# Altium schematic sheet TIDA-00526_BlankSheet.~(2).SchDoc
size 431 x 279 mm; Date: Not shown in title block; ApprovedBy: Not shown in title block; CheckedBy: Not shown in title block; Author: Not shown in title block; CompanyName: Texas Instruments; Engineer: Antony Carvajales; Organization: MDP_RF; Address1: Not shown in title block; Address2: Not shown in title block; Address3: Not shown in title block; Address4: Not shown in title block; DocumentNumber: 1; Revision: Use project parameter SCH_Rev; SheetNumber: 2; SheetTotal: 3; PageSetup: Record=PageOptions¦CenterHorizontal=True¦CenterVertical=True¦PrintScale=1.00¦XCorrection=1.00¦YCorrection=1.00¦PrintKind=0¦BorderSize=5000000¦LeftOffset=0¦BottomOffset=0¦Orientation=2¦PaperLength=1000¦PaperWidth=1000¦Scale=100¦PaperSource=15¦PrintQuality=-3¦MediaType=1¦DitherType=10¦PrintScaleMode=1¦PaperKind=Letter¦PaperIndex=1
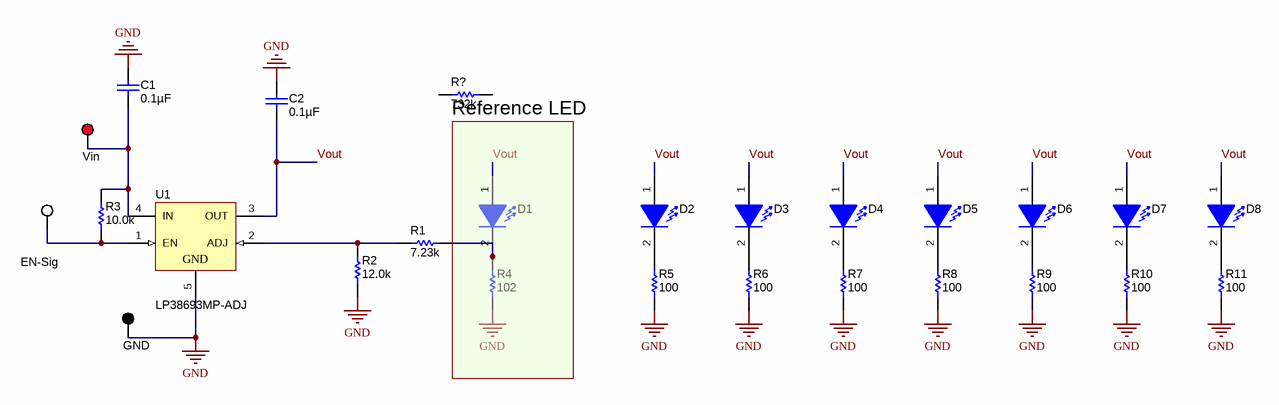
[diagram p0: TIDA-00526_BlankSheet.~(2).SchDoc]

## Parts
C1  ValueDisplayed: 0.1µF  [0805_HV]  (hidden comment: C0805C104K3RACTU)
C2  ValueDisplayed: 0.1µF  [0805_HV]  (hidden comment: C0805C104K3RACTU)
D1  C503D-WAN-CCBDB232  [HLMP-341_YELLOW]  (value not drawn)
D2  C503D-WAN-CCBDB232  [HLMP-341_YELLOW]  (value not drawn)
D3  LED, White, TH  [HLMP-341_YELLOW]  (value not drawn)
D4  C503D-WAN-CCBDB232  [HLMP-341_YELLOW]  (value not drawn)
D5  C503D-WAN-CCBDB232  [HLMP-341_YELLOW]  (value not drawn)
D6  C503D-WAN-CCBDB232  [HLMP-341_YELLOW]  (value not drawn)
D7  C503D-WAN-CCBDB232  [HLMP-341_YELLOW]  (value not drawn)
D8  C503D-WAN-CCBDB232  [HLMP-341_YELLOW]  (value not drawn)
EN-Sig  5002  [Keystone5002]  (value not drawn)
GND  5001  [Keystone5001]  (value not drawn)
R1  ValueDisplayed: 7.23k  [0603]  (hidden comment: RT0603DRE077K23L)
R2  ValueDisplayed: 12.0k  [0603]  (hidden comment: RC0603FR-0712KL)
R3  ValueDisplayed: 10.0k  [0603]  (hidden comment: CRCW060310K0FKEA)
R4  ValueDisplayed: 102  [0603]  (hidden comment: CRCW0603102RFKEA)
R5  ValueDisplayed: 100  [0603]  (hidden comment: RC0603FR-07100RL)
R6  ValueDisplayed: 100  [0603]  (hidden comment: RC0603FR-07100RL)
R7  ValueDisplayed: 100  [0603]  (hidden comment: RC0603FR-07100RL)
R8  ValueDisplayed: 100  [0603]  (hidden comment: RC0603FR-07100RL)
R9  ValueDisplayed: 100  [0603]  (hidden comment: RC0603FR-07100RL)
R10  ValueDisplayed: 100  [0603]  (hidden comment: RC0603FR-07100RL)
R11  ValueDisplayed: 100  [0603]  (hidden comment: RC0603FR-07100RL)
R?  ValueDisplayed: 732k  [0603]  (hidden comment: RC0603FR-07732KL)
U1  LP38693MP-ADJ  [MP05A_N]
Vin  5000  [Keystone5000]  (value not drawn)

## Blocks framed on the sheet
Reference LED: D1 R4

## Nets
GND: C1.1 C2.1 GND.1 R2.1 R4.1 R5.1 R6.1 R7.1 R8.1 R9.1 R10.1 R11.1 U1.5(GND)
Vout: C2.2 D1.1(A) D2.1(A) D3.1(A) D4.1(A) D5.1(A) D6.1(A) D7.1(A) D8.1(A) U1.3(OUT)
NetC1_2: C1.2 R3.2 U1.4(IN) Vin.1
NetD1_2: D1.2(K) R1.2 R4.2
NetD2_2: D2.2(K) R5.2
NetD3_2: D3.2(K) R6.2
NetD4_2: D4.2(K) R7.2
NetD5_2: D5.2(K) R8.2
NetD6_2: D6.2(K) R9.2
NetD7_2: D7.2(K) R10.2
NetD8_2: D8.2(K) R11.2
NetEN-Sig_1: EN-Sig.1 R3.1 U1.1(EN)
NetR1_1: R1.1 R2.2 U1.2(ADJ)

Not connected (* = marked no-connect by the designer): R? 1 2

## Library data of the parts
C1 C2 = C0805C104K3RACTU: CAP, CERM, 0.1 µF, 25 V, +/- 10%, X7R, 0805; Manufacturer: Kemet; Polarized: N; CompType: Capacitor; Value: 0.1uF; U/M: EA; Cap_F: 0.0000001; Tolerance_%: 10; ESR_ohm: 0.064; Value1: 0.064 ohm; VDC_V: 25; Value2: 25V; IRMS_A: 1.64; TaMin_C: -55; TaMax_C: 125; Cap_Case: 0805
D1 D2 D4 D5 D7 D8 = HLMP-3416: LED, White, TH; Manufacturer: CREE
D3 = HLMP-3416: Manufacturer: CREE; PartNumber: C503D-WAN-CCBDB232
D6 = HLMP-3416: LED, white, TH; Manufacturer: CREE
EN-Sig = 5002: Test Point, Miniature, White, TH; Manufacturer: Keystone; CompType: Test Point Loop; U/M: EA
GND = 5001: Test Point, Miniature, Black, TH; Manufacturer: Keystone; CompType: Test Point Loop; U/M: EA
R1 = RT0603DRE077K23L: RES, 7.23 k, 0.5%, 0.1 W, 0603; Manufacturer: Yageo America; CompType: Resistor; Value: 7.23k; Res_ohm: 7230; Value_Code: 7k23; Tolerance_%: 0.5; Power_W: 0.1; Value2: 0.1W; VDC_V: 75; TempCo: 50 ppm/C; EIA_Code: E192; U/M: EA
R2 = RC0603FR-0712KL: RES, 12.0 k, 1%, 0.1 W, 0603; Manufacturer: Yageo America; CompType: Resistor; Value: 12.0k; Res_ohm: 12000; Value_Code: 12k0; Tolerance_%: 1; Power_W: 0.1; Value2: 0.1W; VDC_V: 150; TempCo: 200 ppm/C; U/M: EA
R3 = CRCW060310K0FKEA: RES, 10.0 k, 1%, 0.1 W, 0603; Manufacturer: Vishay-Dale; CompType: Resistor; Value: 10.0k; Res_ohm: 10000; Value_Code: 10k0; Tolerance_%: 1; Power_W: 0.1; Value2: 0.1W; VDC_V: 75; TempCo: 100 ppm/C; EIA_Code: E96; U/M: EA
R4 = CRCW0603102RFKEA: RES, 102, 1%, 0.1 W, 0603; Manufacturer: Vishay-Dale; CompType: Resistor; Value: 102; Value_Code: 102R; Tolerance_%: 1; Power_W: 0.1; Value2: 0.1W; VDC_V: 75; TempCo: 100 ppm/C; EIA_Code: E96; U/M: EA
R5-R11 = RC0603FR-07100RL: RES, 100, 1%, 0.1 W, 0603; Manufacturer: Yageo America; CompType: Resistor; Value: 100; Value_Code: 100R; Tolerance_%: 1; Power_W: 0.1; Value2: 0.1W; VDC_V: 150; TempCo: 200 ppm/C; EIA_Code: E96; U/M: EA
R? = RC0603FR-07732KL: RES, 732 k, 1%, 0.1 W, 0603; Manufacturer: Yageo America; CompType: Resistor; Value: 732k; Res_ohm: 732000; Tolerance_%: 1; Power_W: 0.1; Value2: 0.1W; VDC_V: 150; TempCo: 200 ppm/C; EIA_Code: E96; U/M: EA
U1 = LP38693MP-ADJ: 500mA Low Dropout CMOS Linear Regulators, 5-pin SOT-223; Manufacturer: Texas Instruments; PackageTopMarking: XYTT*LJUB; PowerWise: Y; CompType: LDO IC
Vin = 5000: Test Point, Miniature, Red, TH; Manufacturer: Keystone; CompType: Test Point Loop; U/M: EA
